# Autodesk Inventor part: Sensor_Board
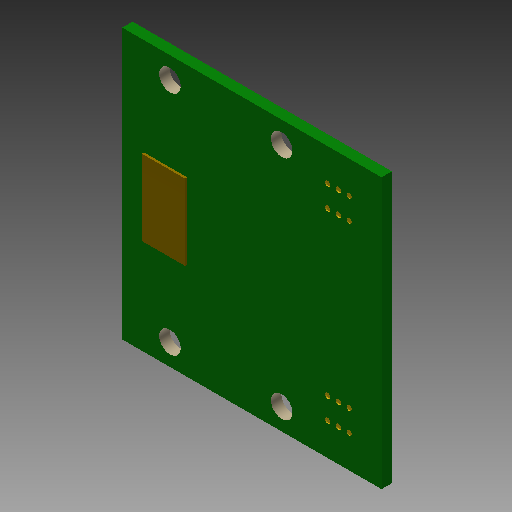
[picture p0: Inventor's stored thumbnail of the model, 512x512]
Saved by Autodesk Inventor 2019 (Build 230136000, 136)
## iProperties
Created: 2015-10
Part Number: Sensor_Board
Material: Generic
Document SubType Name: Modeling
Designer: Chris
Density: 1 g/cm^3
Appearance: Default
Author: Chris
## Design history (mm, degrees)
sketch "Sketch1"
  geometry: L1 (-12, 12.5)-(12, 12.5); L2 (12, 12.5)-(12, -12.5); L3 (12, -12.5)-(-12, -12.5); L4 (-12, -12.5)-(-12, 12.5); 3 further points
  constraints: 8 end point, 2 midpoint, 2 parallel, 1 horizontal, 1 horizontal alignment, 1 perpendicular, 1 vertical alignment
  dimensions: "d0" = 24 distance of L1.start L1.end; "d1" = 25 distance of L3.end L1.start
extrude "Extrusion1" new body sketch "Sketch1" distance "d2" = 0.96; taper "d3" = 0 deg
sketch "Sketch2"
  geometry: L1 (12, -12.5)-(12, 12.5) reference; L2 (-16.8, 0)-(16.8, 0) reference; L3 (12, 12.5)-(-12, 12.5) reference; 5 further points
  constraints: 2 horizontal alignment, 2 vertical alignment, 1 symmetric about line
  dimensions: "d4" = 9.24 distance from line of L1 point (2.76, 10.5); "d5" = 10.34 distance of point (2.76, 10.5) point (-7.58, 10.5); "d6" = 2 distance from line of L3 point (-7.58, 10.5)
hole "Hole1" sketch "Sketch2" at (-7.58, 10.5), (2.76, 10.5), (2.76, -10.5), (-7.58, -10.5) diameter "d7" = 2; stored, may be unused: countersink angle "d11" = 90 deg, drill point angle "d13" = 118 deg; dims "d8" = 6, "d9" = 4, "d10" = 2, "d12" = 8
sketch "Sketch3"
  geometry: L1 (-6, -3.5)-(-10, -3.5); L2 (-10, -3.5)-(-10, 3.5); L3 (-10, 3.5)-(-6, 3.5); L4 (-6, 3.5)-(-6, -3.5); L5 (-16.8, 0)-(16.8, 0) reference; L6 (-12, 12.5)-(-12, -12.5) reference; 1 further point
  constraints: 8 end point, 2 parallel, 1 horizontal, 1 perpendicular, 1 other
  dimensions: "d14" = 7 distance of L1.end L2.end; "d15" = 2 distance between parallel lines of L6 L2; "d16" = 4 distance of L1.start L1.end
extrude "Extrusion2" join sketch "Sketch3" distance "d17" = 0.2; taper "d18" = 0 deg
sketch "Sketch4"
  geometry: L1 (12, -12.5)-(12, 12.5) reference; L2 (12, 12.5)-(-12, 12.5) reference; C1 r 0.25 at (9, 7.5); C2 r 0.25 at (8, 7.5); C3 r 0.25 at (7, 7.5); C4 r 0.25 at (9, 9.5); C5 r 0.25 at (8, 9.5); C6 r 0.25 at (7, 9.5); 1 further point
  constraints: 6 centre point, 1 horizontal, 1 vertical, 10 other
  dimensions: "d19" = 0.5 diameter of C1; "d20" = 3 distance from line of C1.centre L1; "d21" = 5 distance from line of L2 C1.centre; "d24" = 1 distance of C1.centre C2.centre; "d27" = 2 distance of C1.centre C4.centre
extrude "Extrusion3" cut sketch "Sketch4" distance "d30" = 0.1; taper "d31" = 0 deg
mirror "Mirror1"
body "Solid1"
